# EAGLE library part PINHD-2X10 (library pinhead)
PIN HEADER
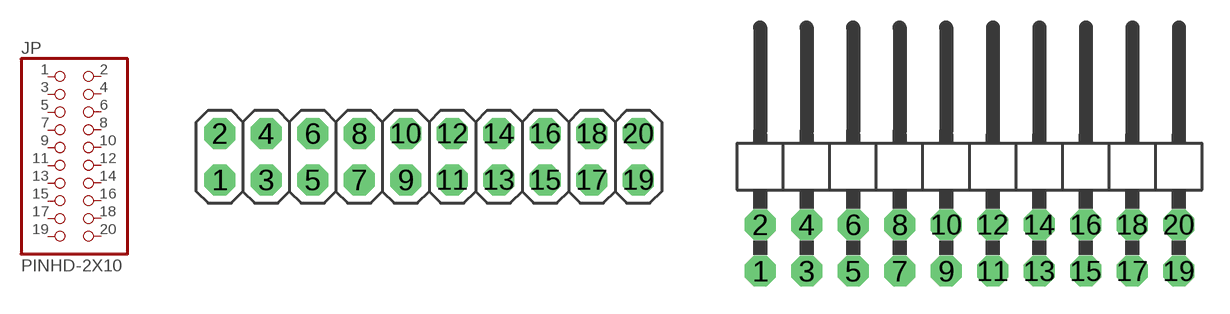
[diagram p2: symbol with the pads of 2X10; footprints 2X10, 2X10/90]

Designator prefix JP

## PINHD-2X10  [2X10]
1  1  pas
2  2  pas
3  3  pas
4  4  pas
5  5  pas
6  6  pas
7  7  pas
8  8  pas
9  9  pas
10  10  pas
11  11  pas
12  12  pas
13  13  pas
14  14  pas
15  15  pas
16  16  pas
17  17  pas
18  18  pas
19  19  pas
20  20  pas

## PINHD-2X10/90  [2X10/90]
Pads as for 2X10

## Footprint 2X10 (pad centres in mm)
PIN HEADER
drill 1.016 pad 1.67 octagon: 1 -11.43,-1.27; 2 -11.43,1.27; 3 -8.89,-1.27; 4 -8.89,1.27; 5 -6.35,-1.27; 6 -6.35,1.27; 7 -3.81,-1.27; 8 -3.81,1.27; 9 -1.27,-1.27; 10 -1.27,1.27; 11 1.27,-1.27; 12 1.27,1.27; 13 3.81,-1.27; 14 3.81,1.27; 15 6.35,-1.27; 16 6.35,1.27; 17 8.89,-1.27; 18 8.89,1.27; 19 11.43,-1.27; 20 11.43,1.27

## Footprint 2X10/90 (pad centres in mm)
PIN HEADER
drill 1.016 pad 1.67 octagon: 1 -11.43,-6.35; 2 -11.43,-3.81; 3 -8.89,-6.35; 4 -8.89,-3.81; 5 -6.35,-6.35; 6 -6.35,-3.81; 7 -3.81,-6.35; 8 -3.81,-3.81; 9 -1.27,-6.35; 10 -1.27,-3.81; 11 1.27,-6.35; 12 1.27,-3.81; 13 3.81,-6.35; 14 3.81,-3.81; 15 6.35,-6.35; 16 6.35,-3.81; 17 8.89,-6.35; 18 8.89,-3.81; 19 11.43,-6.35; 20 11.43,-3.81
